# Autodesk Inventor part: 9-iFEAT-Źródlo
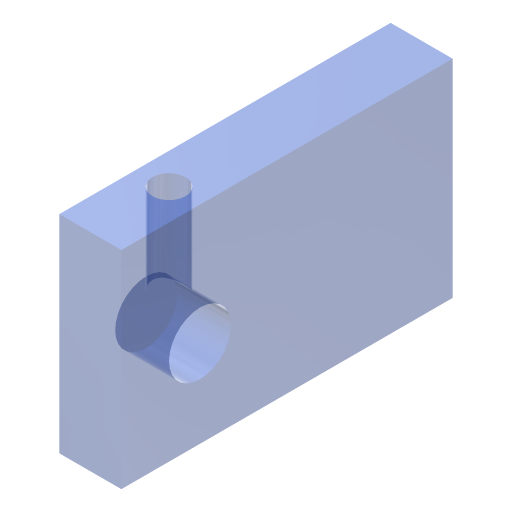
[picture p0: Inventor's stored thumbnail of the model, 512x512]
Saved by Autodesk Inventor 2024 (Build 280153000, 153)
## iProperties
Company: ATC
Shininess: 64.0
Length Units: 11269
Angle Units: 11279
Time Units: 11290
Mass Units: 11283
Length Display Precision: 3
Angle Display Precision: 2
Compacted: True
Part Number: 9-iFEAT-Źródlo
Document SubType Name: Modeling
Created: 2023-03
Material: AJ-PL-1
Designer: Andrzej Jaskulski
Manufacturer: Standard
Standards Organization: Custom
Density: 0.68 g/cm^3
Appearance: Przezroczysty — niebieski
Checked By: A.J.
Engr Approved By: Andrzej Jaskulski
Mfg Approved By: Andrzej Jaskulski
Authority: A.J.
Density: 0.0
Volumn: 0.0
Area: 0.0
PropertySet Name: Model Information
Control State: 0
Master: False
Checked Out: False
Title: A.J.: Kurs R2024-MEP
Author: Andrzej Jaskulski
Revision Number: 1/24
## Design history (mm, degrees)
sketch "Szkic1"
  geometry: L1 (0, 0)-(15, 0); L2 (15, 0)-(15, 80); L3 (15, 80)-(0, 80); L4 (0, 80)-(0, 0)
  constraints: 8 end point, 2 parallel, 1 horizontal, 1 perpendicular, 1 other
  dimensions: "GRUBplyty" = 15 distance of L1.start L1.end; "d10" = 80 distance of L3.end L1.start
extrude "Wyciągnięcie proste1" new body sketch "Szkic1" distance "d0" = 50; taper "d1" = 0 deg
sketch "Wierc"
  geometry: 1 further point
hole "WIERCONY" sketch "Wierc" at (7.5, 19) diameter "FIwiertla" = 8; stored, may be unused: countersink angle "d6" = 82 deg, drill point angle "d8" = 0 deg; dims "d3" = 6, "d4" = 4, "d5" = 2, "GLEBwiertla" = 29
sketch "Frez"
  geometry: L1 (29, 23)-(29, 15) reference; 1 further point
  constraints: 1 midpoint
hole "FREZOWANY" sketch "Frez" at (29, 19) diameter "FIfreza" = 15; stored, may be unused: countersink angle "d17" = 82 deg, drill point angle "d19" = 0 deg; dims "d14" = 6, "d15" = 4, "d16" = 2, "GLEBfreza" = 13
node "Bryła1"
node "Korpusy bryłowe"
node "Korpusy powierzchniowe"
